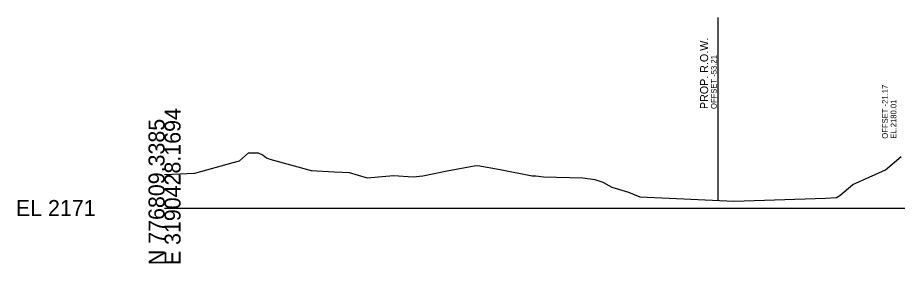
# Model space of a CAD drawing. Extents: x -26 to 303, y -25 to 5046.
# Drawn here: x -25.7 to 128.1, y 3490.3 to 3533.3 of the extents above; entities that cross this region are included whole.
import ezdxf

# ---------------------------------------------------------------- set-up
doc = ezdxf.new("R2010")
doc.units = 0
for name, color, linetype in [('DESIGN - ROW - Right-of-Way and Easement Labels', 7, 'Continuous'), ('DESIGN - ROW - Right-of-Way Linework', 7, 'Continuous'), ('DESIGN - SHEET - Light Grid', 7, 'Continuous'), ('DESIGN - TYPICAL - Slope Tie Text', 7, 'Continuous'), ('SURVEY - GROUND - Top of Ground', 7, 'Continuous')]:
    doc.layers.add(name, color=color, linetype=linetype)

msp = doc.modelspace()

# ---------------------------------------------------------------- linework, layer by layer
at = {"layer": 'DESIGN - ROW - Right-of-Way Linework'}
msp.add_line((96.79, 3501.32), (96.79, 3533.32), dxfattribs=at)
at = {"layer": 'DESIGN - SHEET - Light Grid'}
msp.add_line((0, 3500), (150, 3500), dxfattribs=at)
at = {"layer": 'SURVEY - GROUND - Top of Ground'}
msp.add_lwpolyline([(0, 3505.86), (5.3, 3506.12), (11.97, 3507.95), (13.1, 3508.28), (14.67, 3509.65), (16.36, 3509.67), (17.27, 3509.23), (17.8, 3508.78), (18.39, 3508.54), (25.65, 3506.54), (29.66, 3506.34), (31.03, 3506.29), (32.27, 3506.2), (35.43, 3505.26), (40.02, 3505.67), (43.49, 3505.48), (45.17, 3505.62), (49.41, 3506.53), (54.15, 3507.36), (54.77, 3507.44), (58.7, 3506.77), (64.26, 3505.63), (64.91, 3505.63), (66.25, 3505.47), (73.14, 3505.28), (75.21, 3505.02), (76.65, 3504.52), (78.23, 3503.65), (81.12, 3502.75), (83.1, 3501.94), (90.82, 3501.61), (99.56, 3501.19), (115.55, 3501.75), (117.49, 3501.85), (118.07, 3502.17), (120.34, 3504.14), (126.08, 3506.7), (128.81, 3508.99)], dxfattribs=at)

# ---------------------------------------------------------------- texts
at = {"layer": 'DESIGN - ROW - Right-of-Way and Easement Labels'}
for s, height, p in [('PROP. R.O.W.', 1.4, (95.04, 3517.32)), ('OFFSET -53.21', 1, (96.54, 3517.32))]:
    msp.add_text(s, height=height, rotation=90, dxfattribs=at).set_placement(p)
at = {"layer": 'DESIGN - SHEET - Light Grid'}
for s, p in [('E 3190428.1694', (2.8, 3490)), ('N 776809.3385', (0, 3490))]:
    msp.add_text(s, height=2.8, rotation=90, dxfattribs=at).set_placement(p)
msp.add_text('EL 2171', height=2.8, dxfattribs=at).set_placement((-26, 3498.6))
at = {"layer": 'DESIGN - TYPICAL - Slope Tie Text'}
for s, p in [('OFFSET -21.17', (126.46, 3512.13)), ('EL.2180.01', (127.96, 3512.13))]:
    msp.add_text(s, height=1, rotation=90, dxfattribs=at).set_placement(p)

doc.saveas('drawing.dxf')
